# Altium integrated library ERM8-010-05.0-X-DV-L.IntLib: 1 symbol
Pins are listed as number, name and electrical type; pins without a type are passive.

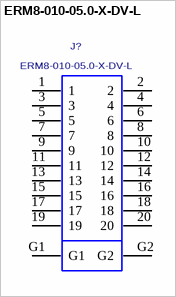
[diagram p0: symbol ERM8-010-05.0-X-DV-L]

## ERM8-010-05.0-X-DV-L
designator J?
0.8mm Edge Rate Terminal Assembly, Double Vertical Row, 20 Pins.; MANUFACTURER: SAMTEC
footprint ERM8-010-05.0-X-DV-L
pins: 1, 2, 3, 4, 5, 6, 7, 8, 9, 10, 11, 12, 13, 14, 15, 16, 17, 18, 19, 20, G1, G2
